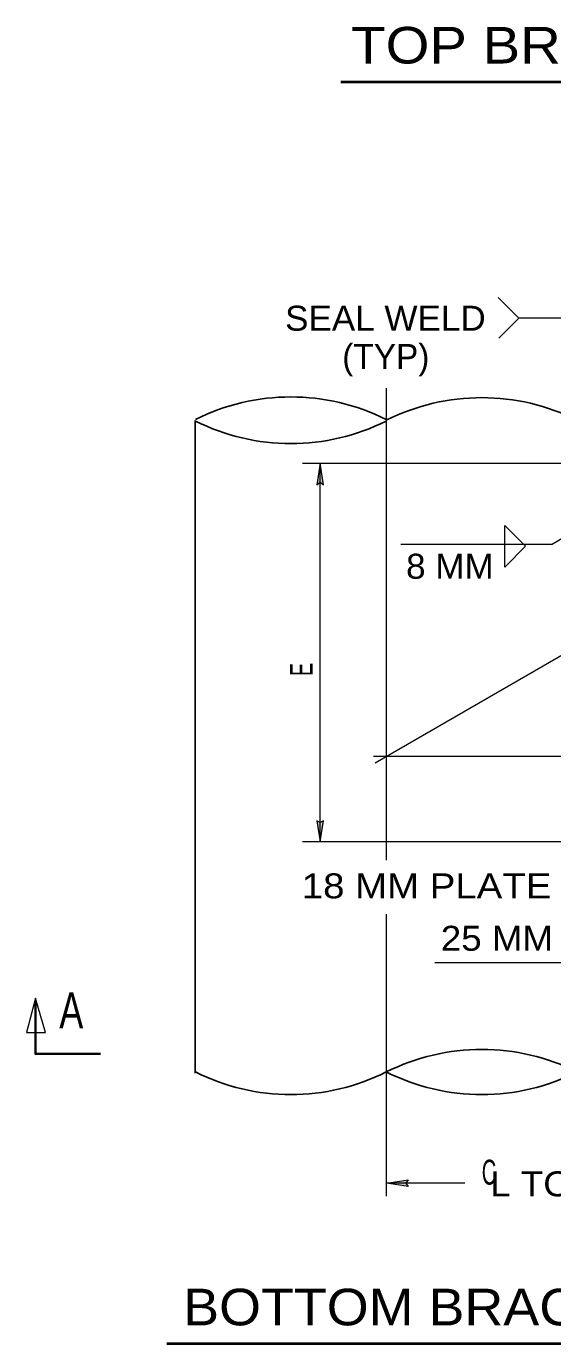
# Model space of a CAD drawing. Extents: x 312601.858 to 312602.699, y 144420.109 to 144420.704.
# Drawn here: x 312602.1052 to 312602.1684, y 144420.3549 to 144420.5132 of the extents above; entities that cross this region are included whole.
import ezdxf
from ezdxf.enums import TextEntityAlignment as Align

# ---------------------------------------------------------------- set-up
doc = ezdxf.new("R2010")
doc.units = 0
doc.header["$LTSCALE"] = 0.0012
doc.linetypes.add('DOT_DASHED', pattern=[7.7, 5, -1.2, 0.3, -1.2])
for name, color, linetype, lineweight in [('1', 7, 'Continuous', 25), ('2', 7, 'Continuous', 13), ('39', 7, 'Continuous', 13), ('9', 7, 'Continuous', 13)]:
    doc.layers.add(name, color=color, linetype=linetype, lineweight=lineweight)

msp = doc.modelspace()

# ---------------------------------------------------------------- hatches: boundary and pattern name
at = {"layer": '39'}
for points in [[(312602.1405, 144420.4584), (312602.1409, 144420.4581), (312602.1405, 144420.4607), (312602.1401, 144420.4581)], [(312602.1405, 144420.4584), (312602.1409, 144420.4581), (312602.1405, 144420.4607), (312602.1401, 144420.4581)], [(312602.1405, 144420.4175), (312602.1401, 144420.4177), (312602.1405, 144420.4152), (312602.1409, 144420.4177)], [(312602.1508, 144420.3742), (312602.1511, 144420.3738), (312602.1485, 144420.3742), (312602.1511, 144420.3746)]]:
    msp.add_hatch(color=256, dxfattribs=at).paths.add_polyline_path(points)

# ---------------------------------------------------------------- linework, layer by layer
at = {"layer": '1', "linetype": 'DOT_DASHED', "lineweight": 13}
for p, q in [((312602.1485, 144420.413), (312602.1485, 144420.4697)), ((312602.1471, 144420.4247), (312602.2042, 144420.4576)), ((312602.1469, 144420.4255), (312602.2336, 144420.4255)), ((312602.1485, 144420.3805), (312602.1485, 144420.4065))]:
    msp.add_line(p, q, dxfattribs=at)
at = {"layer": '1'}
msp.add_line((312602.1255, 144420.4658), (312602.1255, 144420.3874), dxfattribs=at)
at = {"layer": '1', "lineweight": 13}
for p, q in [((312602.1384, 144420.4607), (312602.1697, 144420.4607)), ((312602.1405, 144420.4157), (312602.1405, 144420.4607)), ((312602.1683, 144420.4509), (312602.1502, 144420.4509)), ((312602.1697, 144420.4152), (312602.1384, 144420.4152)), ((312602.1543, 144420.4007), (312602.1714, 144420.4007)), ((312602.1485, 144420.3726), (312602.1485, 144420.3842)), ((312602.1579, 144420.3742), (312602.1485, 144420.3742))]:
    msp.add_line(p, q, dxfattribs=at)
at = {"layer": '1', "lineweight": 35}
msp.add_lwpolyline([(312602.1063, 144420.396), (312602.1063, 144420.3897), (312602.1141, 144420.3897)], dxfattribs=at)
at = {"layer": '2', "lineweight": 40}
for p, q in [((312602.143, 144420.5065), (312602.2189, 144420.5065)), ((312602.1221, 144420.3549), (312602.2121, 144420.3549))]:
    msp.add_line(p, q, dxfattribs=at)
at = {"layer": '2'}
msp.add_line((312602.178, 144420.4781), (312602.1644, 144420.4781), dxfattribs=at)
for points in [[(312602.1619, 144420.4806), (312602.1644, 144420.4781), (312602.162, 144420.4757)], [(312602.1683, 144420.4509), (312602.1766, 144420.4558), (312602.1714, 144420.4588)]]:
    msp.add_lwpolyline(points, dxfattribs=at)
msp.add_lwpolyline([(312602.1627, 144420.4482), (312602.1627, 144420.4532), (312602.1652, 144420.4507)], close=True, dxfattribs=at)
at = {"layer": '2', "lineweight": 25}
for centre, start, end in [((312602.136985, 144420.443031), 63.38393, 116.61607), ((312602.159935, 144420.442941), 63.38393, 116.61607), ((312602.136985, 144420.488649), 243.38393, 296.61607), ((312602.159935, 144420.364641), 63.38393, 116.61607), ((312602.136985, 144420.410439), 243.38393, 296.61607), ((312602.159935, 144420.410439), 243.38393, 296.61607)]:
    msp.add_arc(centre, 0.025613, start, end, dxfattribs=at)
at = {"layer": '39'}
for points in [[(312602.1405, 144420.4584), (312602.1409, 144420.4581), (312602.1405, 144420.4607), (312602.1401, 144420.4581)], [(312602.1405, 144420.4584), (312602.1409, 144420.4581), (312602.1405, 144420.4607), (312602.1401, 144420.4581)], [(312602.1405, 144420.4175), (312602.1401, 144420.4177), (312602.1405, 144420.4152), (312602.1409, 144420.4177)], [(312602.1508, 144420.3742), (312602.1511, 144420.3738), (312602.1485, 144420.3742), (312602.1511, 144420.3746)]]:
    msp.add_lwpolyline(points, close=True, dxfattribs=at)
at = {"layer": '9'}
msp.add_lwpolyline([(312602.1052, 144420.3923), (312602.1075, 144420.3923), (312602.1063, 144420.3964)], close=True, dxfattribs=at)

# ---------------------------------------------------------------- texts
at = {"layer": '1', "width": 1.15}
msp.add_text('18 MM PLATE', height=0.003, dxfattribs=at).set_placement((312602.1383, 144420.4084))
at = {"layer": '2'}
for s, height, width, p in [('TOP BRACKET DETAIL', 0.0044, 1.15, (312602.1809, 144420.5087)), ('SEAL WELD', 0.003, 1.05, (312602.14835, 144420.4766)), ('8 MM', 0.003, 1.05, (312602.1561, 144420.4468)), ('25 MM', 0.003, 1.1, (312602.16175, 144420.4021)), ('A', 0.0043, 0.75, (312602.1106, 144420.3928)), ('C', 0.003, 0.6, (312602.1608, 144420.374)), ('L TOWER SHAFT', 0.003, 1.1, (312602.17885, 144420.3726)), ('BOTTOM BRACKET DETAIL', 0.0044, 1.1, (312602.1663, 144420.3571))]:
    msp.add_text(s, height=height, dxfattribs=dict(at, width=width)).set_placement(p, align=Align.CENTER)
msp.add_text('(TYP)', height=0.003, dxfattribs=at).set_placement((312602.1484, 144420.472), align=Align.CENTER)
at = {"layer": '2', "width": 0.65}
msp.add_text('E', height=0.0027, rotation=90, dxfattribs=at).set_placement((312602.1396, 144420.4359), align=Align.CENTER)

doc.saveas('drawing.dxf')
